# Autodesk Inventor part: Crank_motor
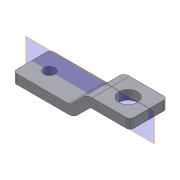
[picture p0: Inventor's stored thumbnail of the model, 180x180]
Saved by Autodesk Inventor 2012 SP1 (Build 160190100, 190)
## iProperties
Created: 2006-03
Part Number: Crank_motor
Document SubType Name: Modeling
Material: Stainless Steel, 440C
Mass: 46.8107 g
Surface Area: 35.1137 cm^2
Volume: 6.04008 cm^3
Density: 7.75 g/cm^3
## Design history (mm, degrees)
sketch "Sketch1"
  geometry: L1 (0, 0)-(-22.16, 0); L2 (0, 0)-(9, -9); L3 (9, -9)-(40.46, -9)
  constraints: 6 end point, 1 horizontal, 1 parallel
  dimensions: "d0" = 135 deg angle of L2 L1; "d1" = 62.62 horizontal distance of L3.end L1.end; "d2" = 22.16 distance of L1.start L1.end; "d3" = 9 distance between parallel lines of L3 L1
workplane "Work Plane1"
sketch "Sketch2"
  geometry: L1 (-10, 2.5)-(10, 2.5); L2 (10, 2.5)-(10, -2.5); L3 (10, -2.5)-(-10, -2.5); L4 (-10, -2.5)-(-10, 2.5); L5 (-10, 2.5)-(10, -2.5); 2 further points
  constraints: 10 end point, 2 parallel, 1 coincident, 1 horizontal, 1 midpoint, 1 perpendicular
  dimensions: "d4" = 20 distance of L1.start L1.end; "d5" = 5 distance of L3.end L1.start
sweep "Sweep1" sketch "Sketch2" dims "d6" = 0
fillet "Fillet1" dims "d7" = 7
fillet "Fillet2" dims "d8" = 2
sketch "Sketch3"
  geometry: L1 (-6.262, 10)-(81.406, 10) reference; L2 (0, 20)-(0, 0) reference; C1 r 3.05 at (9.5, 10); 1 further point
  constraints: 1 centre point, 1 point on line
  dimensions: "d9" = 9.5 distance from line of C1.centre L2; "d10" = 6.1 diameter of C1
extrude "Extrusion1" cut sketch "Sketch3" stored distance "d11" = 10; taper "d12" = 0 deg
sketch "Sketch4"
  geometry: L1 (-68.882, 10)-(18.786, 10) reference; L2 (0, 26)-(0, -2) reference; C1 r 5 at (-11, 10); 1 further point
  constraints: 1 centre point, 1 point on line
  dimensions: "d13" = 11 distance from line of C1.centre L2; "d14" = 10 diameter of C1
extrude "Extrusion2" cut sketch "Sketch4" stored distance "d15" = 10; taper "d16" = 0 deg
fillet "Fillet3" dims "d17" = 2
node "Mobile"
body "Solid1"
